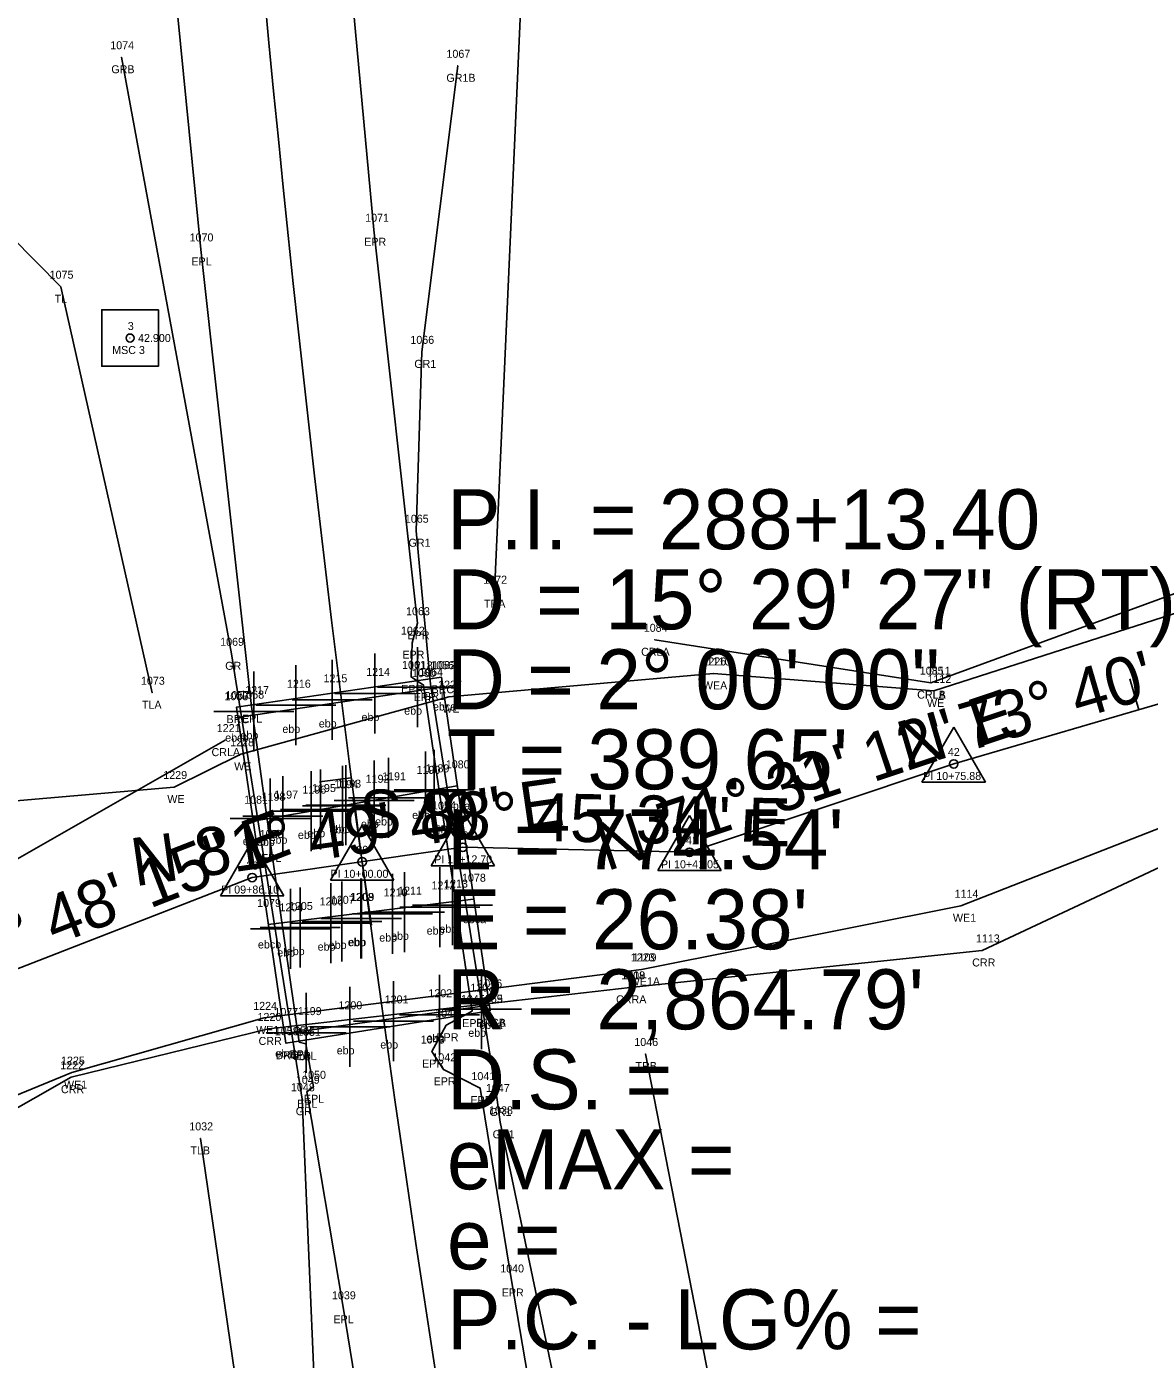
# Model space of a CAD drawing. Extents: x 2445178 to 2446205, y 790762 to 792372.
# Drawn here: x 2445671.4 to 2445811.8, y 791731.8 to 791898.3 of the extents above; entities that cross this region are included whole.
import ezdxf

# ---------------------------------------------------------------- set-up
doc = ezdxf.new("R2010")
doc.units = 0
for name, color, linetype in [('RD_EX_Bridge', 7, 'Continuous'), ('RD_EX_Bridge_txCode', 7, 'Continuous'), ('RD_EX_GuardRail', 7, 'Continuous'), ('RD_EX_GuardRail_txCode', 7, 'Continuous'), ('RD_EX_H2O', 7, 'Continuous'), ('RD_EX_H2O_txCode', 7, 'Continuous'), ('RD_EX_Misc', 7, 'Continuous'), ('RD_EX_Misc_txCode', 7, 'Continuous'), ('RD_EX_Road', 7, 'Continuous'), ('RD_EX_Road_txCode', 7, 'Continuous'), ('RD_EX_VEG', 7, 'Continuous'), ('RD_EX_VEG_txCode', 7, 'Continuous'), ('RD_HC_Cl', 7, 'Continuous'), ('RD_HC_Data', 7, 'Continuous'), ('RD_HC_Data_Tic', 7, 'Continuous'), ('RD_HC_Survey', 7, 'Continuous'), ('RD_HC_txCode', 7, 'Continuous'), ('RD_SMD_Locator', 7, 'Continuous')]:
    doc.layers.add(name, color=color, linetype=linetype)

msp = doc.modelspace()

# ---------------------------------------------------------------- linework, layer by layer
at = {"layer": 'RD_EX_Bridge'}
msp.add_lwpolyline([(2445729.38, 791775.32), (2445723.31, 791817.01), (2445697.69, 791813.27), (2445703.85, 791771.27), (2445729.38, 791775.32)], dxfattribs=at)
at = {"layer": 'RD_EX_GuardRail'}
for points in [[(2445705.68, 791695.08), (2445707.49, 791727.11), (2445705.87, 791764.26), (2445697.05, 791819.94), (2445683.29, 791894.5)], [(2445745.83, 791688.99), (2445730.65, 791761.38), (2445730.26, 791764.17), (2445721.94, 791816.16), (2445720.14, 791835.32), (2445720.85, 791857.68), (2445725.34, 791893.43)]]:
    msp.add_lwpolyline(points, dxfattribs=at)
at = {"layer": 'RD_EX_H2O'}
for points in [[(2445749.98, 791821.69), (2445784.5, 791816.33), (2445784.5, 791816.33), (2445826.97, 791831.85), (2445864.4, 791840.41), (2445865.35, 791848.28), (2445857.59, 791890.6), (2445862.25, 791903.98), (2445902.88, 791935.07), (2445928.13, 791937.54), (2445982.7, 791973.27), (2446006.36, 791974.66), (2446055.29, 791944.59), (2446112.86, 791944.82), (2446116.06, 791949.26), (2446125.53, 791975.87), (2446156.76, 791972.15), (2446187.24, 792018.21)], [(2445757.3, 791817.48), (2445784.85, 791815.29), (2445827.3, 791828.95), (2445865.88, 791838.48), (2445867.77, 791849.3), (2445858.86, 791890.39), (2445863.96, 791902.52), (2445903.58, 791933.29), (2445928.32, 791935.62), (2445983.75, 791971.59), (2446005.28, 791972.74), (2446055.03, 791943.12), (2446113.69, 791943.23), (2446117.06, 791949.31), (2446126.55, 791974.16), (2446158.67, 791970.49), (2446188.67, 792015.57)], [(2445748.32, 791780.49), (2445788.24, 791788.44), (2445846, 791811.01), (2445891.85, 791826.96), (2445872.2, 791885.31), (2445911.58, 791917.24), (2445942.41, 791930.41), (2445989.95, 791963.2), (2446004.43, 791957.67), (2446037.13, 791928.19), (2446062.94, 791924.63), (2446122.42, 791925.89), (2446133.98, 791956.62), (2446163.05, 791958.48), (2446202.11, 792005.16)], [(2445746.88, 791778.25), (2445790.91, 791782.86), (2445846.87, 791809.11), (2445896.01, 791824.25), (2445877, 791883.78), (2445912.26, 791916.16), (2445942.78, 791927.77), (2445991.6, 791962.06), (2446003.69, 791956.06), (2446036.32, 791927.07), (2446060.96, 791923.67), (2446122.97, 791923.97), (2446134.24, 791956.18), (2446163.21, 791958.01), (2446202.51, 792004.24)], [(2445757.3, 791817.48), (2445724.23, 791814.58), (2445698.23, 791807.38), (2445689.87, 791803.29), (2445658, 791800.52), (2445641.81, 791830.07), (2445642.32, 791839.59), (2445634.31, 791862.06), (2445625.81, 791909.02), (2445601.16, 791980.42)], [(2445696.27, 791809.15), (2445652.77, 791784.32), (2445604.79, 791778.94)], [(2445748.32, 791780.49), (2445701.12, 791774.43), (2445677.09, 791767.59), (2445662.39, 791761.56), (2445644.36, 791766.93), (2445623.55, 791762.71), (2445618.49, 791746.46), (2445607.67, 791748.78), (2445606.64, 791748.27), (2445612.18, 791734.98), (2445561.56, 791692.97), (2445554.1, 791670.89), (2445517.8, 791656.91), (2445473.7, 791621.85), (2445363.77, 791592.3), (2445292.26, 791558.82)], [(2445746.88, 791778.25), (2445701.7, 791773.05), (2445676.99, 791767.02), (2445663.02, 791759.06), (2445644.08, 791765.78), (2445608.19, 791764.17)]]:
    msp.add_lwpolyline(points, dxfattribs=at)
at = {"layer": 'RD_EX_Misc'}
for p, q in [((2445714.97, 791809.98), (2445714.97, 791819.98)), ((2445720.31, 791810.78), (2445720.31, 791820.78)), ((2445705.08, 791808.5), (2445705.08, 791818.5)), ((2445709.63, 791809.18), (2445709.63, 791819.18)), ((2445699.83, 791807.71), (2445699.83, 791817.71)), ((2445723.52, 791815.83), (2445697.56, 791811.94)), ((2445709.97, 791814.98), (2445719.97, 791814.98)), ((2445715.31, 791815.78), (2445725.31, 791815.78)), ((2445700.08, 791813.5), (2445710.08, 791813.5)), ((2445704.63, 791814.18), (2445714.63, 791814.18)), ((2445694.83, 791812.71), (2445704.83, 791812.71)), ((2445714.89, 791796.62), (2445714.89, 791806.62)), ((2445716.67, 791796.93), (2445716.67, 791806.93)), ((2445721.3, 791797.73), (2445721.3, 791807.73)), ((2445722.38, 791797.92), (2445722.38, 791807.92)), ((2445707.01, 791795.26), (2445707.01, 791805.26)), ((2445708.19, 791795.46), (2445708.19, 791805.46)), ((2445710.95, 791795.94), (2445710.95, 791805.94)), ((2445711.34, 791796.01), (2445711.34, 791806.01)), ((2445725.27, 791803.42), (2445699.75, 791799)), ((2445701.89, 791794.37), (2445701.89, 791804.37)), ((2445703.46, 791794.64), (2445703.46, 791804.64)), ((2445709.89, 791801.62), (2445719.89, 791801.62)), ((2445711.67, 791801.93), (2445721.67, 791801.93)), ((2445716.3, 791802.73), (2445726.3, 791802.73)), ((2445717.38, 791802.92), (2445727.38, 791802.92)), ((2445702.01, 791800.26), (2445712.01, 791800.26)), ((2445703.19, 791800.46), (2445713.19, 791800.46)), ((2445705.95, 791800.94), (2445715.95, 791800.94)), ((2445706.34, 791801.01), (2445716.34, 791801.01)), ((2445696.89, 791799.37), (2445706.89, 791799.37)), ((2445698.46, 791799.64), (2445708.46, 791799.64)), ((2445723.12, 791783.29), (2445723.12, 791793.29)), ((2445724.7, 791783.52), (2445724.7, 791793.52)), ((2445710.87, 791781.49), (2445710.87, 791791.49)), ((2445713.24, 791781.84), (2445713.24, 791791.84)), ((2445713.32, 791781.85), (2445713.32, 791791.85)), ((2445717.18, 791782.42), (2445717.18, 791792.42)), ((2445718.67, 791782.63), (2445718.67, 791792.63)), ((2445704.44, 791780.55), (2445704.44, 791790.55)), ((2445705.63, 791780.72), (2445705.63, 791790.72)), ((2445709.48, 791781.29), (2445709.48, 791791.29)), ((2445727.27, 791789.25), (2445701.64, 791786.09)), ((2445718.12, 791788.29), (2445728.12, 791788.29)), ((2445719.7, 791788.52), (2445729.7, 791788.52)), ((2445705.87, 791786.49), (2445715.87, 791786.49)), ((2445708.24, 791786.84), (2445718.24, 791786.84)), ((2445708.32, 791786.85), (2445718.32, 791786.85)), ((2445712.18, 791787.42), (2445722.18, 791787.42)), ((2445713.67, 791787.63), (2445723.67, 791787.63)), ((2445699.44, 791785.55), (2445709.44, 791785.55)), ((2445700.63, 791785.72), (2445710.63, 791785.72)), ((2445704.48, 791786.29), (2445714.48, 791786.29)), ((2445723.06, 791769.81), (2445723.06, 791779.81)), ((2445728.31, 791770.52), (2445728.31, 791780.52)), ((2445711.86, 791768.31), (2445711.86, 791778.31)), ((2445717.31, 791769.04), (2445717.31, 791779.04)), ((2445706.41, 791767.58), (2445706.41, 791777.58)), ((2445729.33, 791776.04), (2445703.81, 791772.47)), ((2445718.06, 791774.81), (2445728.06, 791774.81)), ((2445723.31, 791775.52), (2445733.31, 791775.52)), ((2445706.86, 791773.31), (2445716.86, 791773.31)), ((2445712.31, 791774.04), (2445722.31, 791774.04)), ((2445701.41, 791772.58), (2445711.41, 791772.58))]:
    msp.add_line(p, q, dxfattribs=at)
at = {"layer": 'RD_EX_Road'}
for points in [[(2445780.98, 791497.5), (2445766.72, 791558.1), (2445751.9, 791628.3), (2445743.63, 791673.52), (2445732.07, 791741.61), (2445728.16, 791765.65), (2445723.56, 791768), (2445722.11, 791770.23), (2445723.91, 791773.52), (2445727.13, 791775.28), (2445723.51, 791799.48), (2445721.07, 791816.02), (2445719.51, 791817.06), (2445719.65, 791821.33), (2445720.29, 791823.76), (2445714.87, 791872.94), (2445710.18, 791923.37), (2445705.3, 791989.12), (2445702.81, 792033.07), (2445700.66, 792091.77), (2445697.78, 792201.78), (2445695.41, 792302.8)], [(2445850.42, 791174.36), (2445823.13, 791264.7), (2445806.34, 791321.46), (2445789.41, 791379.89), (2445773.46, 791437.57), (2445759.36, 791494.22), (2445744.01, 791559.83), (2445740.09, 791577.64), (2445731.05, 791621.01), (2445722.21, 791669.43), (2445711, 791738.26), (2445706.49, 791765.2), (2445707.32, 791765.82), (2445706.36, 791771.19), (2445705.53, 791771.38), (2445701.96, 791795.92), (2445699.57, 791813.34), (2445693.24, 791870.48), (2445688.14, 791921.92), (2445683.42, 791987.19), (2445680.88, 792033.67), (2445678.74, 792090.55), (2445675.91, 792199.23), (2445673.61, 792301.11)]]:
    msp.add_lwpolyline(points, dxfattribs=at)
at = {"layer": 'RD_EX_VEG'}
for points in [[(2445687.12, 791815.07), (2445675.71, 791865.82), (2445647.64, 791894.24), (2445625.38, 791951.76), (2445599.8, 791999.43), (2445616.22, 792074.95), (2445645.15, 792198.05), (2445661.49, 792301.38)], [(2445729.92, 791827.7), (2445734.27, 791924.48), (2445719.05, 792048.41), (2445719.1, 792091.3), (2445713.04, 792300.82)], [(2445895.98, 791185.85), (2445831.19, 791390.71), (2445805.05, 791501.58), (2445775.97, 791631.01), (2445748.83, 791769.92)], [(2445660.51, 791562.93), (2445719.21, 791580.62), (2445693.16, 791759.37)]]:
    msp.add_lwpolyline(points, dxfattribs=at)
at = {"layer": 'RD_HC_Cl'}
for p, q in [((2445787.35, 791806.17), (2445829.8, 791818.6)), ((2445754.32, 791795.13), (2445787.35, 791806.17)), ((2445699.64, 791791.97), (2445725.97, 791795.75)), ((2445725.97, 791795.75), (2445754.32, 791795.13)), ((2445661.45, 791777.16), (2445699.64, 791791.97))]:
    msp.add_line(p, q, dxfattribs=at)
msp.add_arc((2448553.48, 792169.37), 2864.79, 181.3527, 196.84356, dxfattribs=at)
at = {"layer": 'RD_HC_Data'}
for p, q in [((2445783.38, 791803.88), (2445787.35, 791810.76)), ((2445787.35, 791810.76), (2445791.32, 791803.88)), ((2445783.38, 791803.88), (2445791.32, 791803.88)), ((2445722, 791793.45), (2445725.97, 791800.33)), ((2445725.97, 791800.33), (2445729.94, 791793.45)), ((2445750.35, 791792.84), (2445754.32, 791799.72)), ((2445754.32, 791799.72), (2445758.29, 791792.84)), ((2445709.43, 791791.65), (2445713.4, 791798.53)), ((2445713.4, 791798.53), (2445717.37, 791791.65)), ((2445695.67, 791789.67), (2445699.64, 791796.55)), ((2445699.64, 791796.55), (2445703.61, 791789.67)), ((2445722, 791793.45), (2445729.94, 791793.45)), ((2445709.43, 791791.65), (2445717.37, 791791.65)), ((2445750.35, 791792.84), (2445758.29, 791792.84)), ((2445695.67, 791789.67), (2445703.61, 791789.67))]:
    msp.add_line(p, q, dxfattribs=at)
for centre in [(2445787.35, 791806.17), (2445725.97, 791795.75), (2445754.32, 791795.13), (2445713.4, 791793.94), (2445699.64, 791791.97)]:
    msp.add_circle(centre, 0.529, dxfattribs=at)
at = {"layer": 'RD_HC_Data_Tic'}
for p, q in [((2445810.5, 791812.95), (2445809.38, 791816.79)), ((2445712.03, 791804.43), (2445708.07, 791803.92)), ((2445713.4, 791793.94), (2445712.27, 791801.86)), ((2445713.4, 791793.94), (2445714.54, 791786.02))]:
    msp.add_line(p, q, dxfattribs=at)
at = {"layer": 'RD_HC_Survey'}
msp.add_lwpolyline([(2445687.91, 791862.94), (2445680.84, 791862.94), (2445680.84, 791855.87), (2445687.91, 791855.87)], close=True, dxfattribs=at)
msp.add_circle((2445684.37, 791859.41), 0.5, dxfattribs=at)
at = {"layer": 'RD_SMD_Locator'}
for centre in [(2445683.29, 791894.5), (2445725.34, 791893.43), (2445714.87, 791872.94), (2445693.24, 791870.48), (2445675.71, 791865.82), (2445684.37, 791859.41), (2445720.85, 791857.68), (2445720.14, 791835.32), (2445729.92, 791827.7), (2445720.29, 791823.76), (2445749.98, 791821.69), (2445697.05, 791819.94), (2445719.65, 791821.33), (2445719.51, 791817.06), (2445723.31, 791817.01), (2445757.3, 791817.48), (2445757.3, 791817.48), (2445687.12, 791815.07), (2445721.07, 791816.02), (2445721.94, 791816.16), (2445784.5, 791816.33), (2445784.5, 791816.33), (2445784.85, 791815.29), (2445697.69, 791813.27), (2445699.57, 791813.34), (2445724.23, 791814.58), (2445696.27, 791809.15), (2445698.23, 791807.38), (2445787.35, 791806.17), (2445689.87, 791803.29), (2445723.51, 791799.48), (2445701.96, 791795.92), (2445725.97, 791795.75), (2445754.32, 791795.13), (2445713.4, 791793.94), (2445699.64, 791791.97), (2445788.24, 791788.44), (2445790.91, 791782.86), (2445748.32, 791780.49), (2445748.32, 791780.49), (2445746.88, 791778.25), (2445746.88, 791778.25), (2445727.13, 791775.28), (2445729.38, 791775.32), (2445729.38, 791775.32), (2445701.12, 791774.43), (2445723.91, 791773.52), (2445701.7, 791773.05), (2445703.85, 791771.27), (2445705.53, 791771.38), (2445706.36, 791771.19), (2445722.11, 791770.23), (2445748.83, 791769.92), (2445676.99, 791767.02), (2445677.09, 791767.59), (2445723.56, 791768), (2445706.49, 791765.2), (2445707.32, 791765.82), (2445728.16, 791765.65), (2445705.87, 791764.26), (2445730.26, 791764.17), (2445730.65, 791761.38), (2445693.16, 791759.37), (2445732.07, 791741.61), (2445711, 791738.26)]:
    msp.add_circle(centre, 0.001, dxfattribs=at)

# ---------------------------------------------------------------- texts
at = {"layer": 'RD_EX_Bridge_txCode'}
for s, p in [('1056', (2445721.9, 791818.01)), ('1057', (2445696.3, 791814.27)), ('BRC', (2445722.06, 791815.01)), ('BRC', (2445696.44, 791811.27)), ('1055', (2445727.99, 791776.32)), ('1059', (2445727.99, 791776.32)), ('1058', (2445702.47, 791772.27)), ('BRCA', (2445727.64, 791773.32)), ('BRCB', (2445727.65, 791773.32)), ('BRC', (2445702.6, 791769.27))]:
    msp.add_text(s, height=1, dxfattribs=at).set_placement(p)
at = {"layer": 'RD_EX_GuardRail_txCode'}
for s, p in [('1074', (2445681.9, 791895.5)), ('1067', (2445723.93, 791894.43)), ('GRB', (2445682.03, 791892.5)), ('GR1B', (2445723.92, 791891.43)), ('1066', (2445719.42, 791858.68)), ('GR1', (2445719.91, 791855.68)), ('1065', (2445718.73, 791836.32)), ('GR1', (2445719.19, 791833.32)), ('1069', (2445695.64, 791820.94)), ('GR', (2445696.27, 791817.94)), ('1064', (2445720.53, 791817.16)), ('GR1', (2445721, 791814.16)), ('1048', (2445704.49, 791765.26)), ('1047', (2445728.87, 791765.17)), ('GR', (2445705.09, 791762.26)), ('1038', (2445729.26, 791762.38)), ('GR1', (2445729.31, 791762.17)), ('GR1', (2445729.7, 791759.38))]:
    msp.add_text(s, height=1, dxfattribs=at).set_placement(p)
at = {"layer": 'RD_EX_H2O_txCode'}
for s, p in [('1084', (2445748.6, 791822.69)), ('CRLA', (2445748.27, 791819.69)), ('1226', (2445755.93, 791818.48)), ('1110', (2445756.48, 791818.48)), ('1085', (2445783.11, 791817.33)), ('1111', (2445784, 791817.33)), ('1227', (2445722.89, 791815.58)), ('WEA', (2445755.99, 791815.48)), ('WEA', (2445755.99, 791815.48)), ('1112', (2445784.07, 791816.29)), ('CRLA', (2445782.78, 791814.33)), ('CRLB', (2445782.79, 791814.33)), ('WE', (2445723.4, 791812.58)), ('WE', (2445784.01, 791813.29)), ('1221', (2445695.21, 791810.15)), ('CRLA', (2445694.56, 791807.15)), ('1228', (2445696.89, 791808.38)), ('WE', (2445697.39, 791805.38)), ('1229', (2445688.53, 791804.29)), ('WE', (2445689.03, 791801.29)), ('1114', (2445787.46, 791789.44)), ('WE1', (2445787.25, 791786.44)), ('1113', (2445790.13, 791783.86)), ('1223', (2445746.97, 791781.49)), ('1109', (2445747.21, 791781.49)), ('CRR', (2445789.66, 791780.86)), ('1108', (2445745.78, 791779.25)), ('1219', (2445745.82, 791779.25)), ('WE1A', (2445746.84, 791778.49)), ('WE1A', (2445746.84, 791778.49)), ('1224', (2445699.77, 791775.43)), ('CRRA', (2445745.14, 791776.25)), ('CRRA', (2445745.14, 791776.25)), ('1220', (2445700.31, 791774.05)), ('WE1', (2445700.13, 791772.43)), ('CRR', (2445700.44, 791771.05)), ('1222', (2445675.64, 791768.02)), ('1225', (2445675.74, 791768.59)), ('WE1', (2445676.11, 791765.59)), ('CRR', (2445675.73, 791765.02))]:
    msp.add_text(s, height=1, dxfattribs=at).set_placement(p)
at = {"layer": 'RD_EX_Misc_txCode'}
for s, p in [('1214', (2445713.9, 791817.18)), ('1218', (2445719.24, 791817.98)), ('1082', (2445722.14, 791818.03)), ('1216', (2445703.99, 791815.7)), ('1215', (2445708.56, 791816.38)), ('1083', (2445696.17, 791814.14)), ('1217', (2445698.77, 791814.91)), ('ebo', (2445718.65, 791812.33)), ('ebca', (2445722.24, 791812.85)), ('ebo', (2445707.97, 791810.73)), ('ebo', (2445713.31, 791811.53)), ('ebcb', (2445696.27, 791808.96)), ('ebo', (2445698.18, 791809.27)), ('ebo', (2445703.42, 791810.05)), ('1080', (2445723.85, 791805.62)), ('1192', (2445713.83, 791803.82)), ('1191', (2445715.89, 791804.13)), ('1190', (2445720.19, 791804.93)), ('1189', (2445721.32, 791805.12)), ('1196', (2445705.92, 791802.46)), ('1195', (2445707.13, 791802.66)), ('1194', (2445709.89, 791803.14)), ('1193', (2445710.28, 791803.21)), ('1081', (2445698.64, 791801.2)), ('1198', (2445700.82, 791801.57)), ('1197', (2445702.4, 791801.84)), ('ebca', (2445723.98, 791800.44)), ('ebo', (2445719.64, 791799.29)), ('ebo', (2445706.54, 791797.02)), ('ebo', (2445709.3, 791797.49)), ('ebo', (2445709.69, 791797.56)), ('ebo', (2445713.24, 791798.18)), ('ebo', (2445715.01, 791798.48)), ('ebcb', (2445698.46, 791796.02)), ('ebo', (2445700.23, 791795.92)), ('ebo', (2445701.81, 791796.2)), ('ebo', (2445705.36, 791796.81)), ('1212', (2445722.06, 791790.49)), ('1213', (2445723.64, 791790.72)), ('1078', (2445725.88, 791791.45)), ('1208', (2445711.86, 791789.04)), ('1209', (2445711.94, 791789.05)), ('1210', (2445716.08, 791789.62)), ('1211', (2445717.89, 791789.83)), ('1079', (2445700.26, 791788.29)), ('1204', (2445703.05, 791787.75)), ('1205', (2445704.24, 791787.92)), ('1206', (2445708.07, 791788.49)), ('1207', (2445709.48, 791788.69)), ('ebca', (2445725.98, 791786.27)), ('ebo', (2445715.53, 791783.97)), ('ebo', (2445717.01, 791784.19)), ('ebo', (2445721.46, 791784.84)), ('ebo', (2445723.05, 791785.07)), ('ebcb', (2445700.36, 791783.11)), ('ebo', (2445702.78, 791782.1)), ('ebo', (2445703.97, 791782.28)), ('ebo', (2445707.83, 791782.84)), ('ebo', (2445709.22, 791783.05)), ('ebo', (2445711.59, 791783.39)), ('ebo', (2445711.67, 791783.41)), ('1203', (2445726.93, 791777.72)), ('1076', (2445727.92, 791778.24)), ('1200', (2445710.43, 791775.51)), ('1201', (2445716.21, 791776.24)), ('1202', (2445721.67, 791777.01)), ('1077', (2445702.42, 791774.67)), ('1199', (2445705.35, 791774.78)), ('ebo', (2445726.66, 791772.07)), ('ebca', (2445728.04, 791773.06)), ('ebo', (2445715.66, 791770.6)), ('ebo', (2445721.41, 791771.37)), ('ebcb', (2445702.52, 791769.49)), ('ebo', (2445704.75, 791769.14)), ('ebo', (2445710.21, 791769.87))]:
    msp.add_text(s, height=1, dxfattribs=at).set_placement(p)
at = {"layer": 'RD_EX_Road_txCode'}
for s, p in [('1071', (2445713.77, 791873.94)), ('1070', (2445691.82, 791871.48)), ('EPR', (2445713.65, 791870.94)), ('EPL', (2445692.04, 791868.48)), ('42.900', (2445685.37, 791858.91)), ('1063', (2445718.88, 791824.76)), ('1062', (2445718.24, 791822.33)), ('EPR', (2445719.06, 791821.76)), ('EPR', (2445718.42, 791819.33)), ('1061', (2445718.38, 791818.06)), ('1060', (2445719.62, 791817.02)), ('1068', (2445698.16, 791814.34)), ('EPR', (2445718.28, 791815.06)), ('EPR', (2445719.84, 791814.02)), ('EPL', (2445698.37, 791811.34)), ('1054', (2445722.13, 791800.48)), ('EPR', (2445722.28, 791797.48)), ('1053', (2445700.58, 791796.92)), ('EPL', (2445700.76, 791793.92)), ('1045', (2445725.74, 791776.28)), ('1044', (2445722.52, 791774.52)), ('1052', (2445704.14, 791772.38)), ('1051', (2445705.26, 791772.19)), ('EPR', (2445725.9, 791773.28)), ('1043', (2445720.72, 791771.23)), ('EPR', (2445722.68, 791771.52)), ('EPL', (2445704.32, 791769.38)), ('EPL', (2445705.16, 791769.19)), ('1042', (2445722.17, 791769)), ('EPR', (2445720.88, 791768.23)), ('1049', (2445705.1, 791766.2)), ('1050', (2445705.89, 791766.82)), ('EPR', (2445722.33, 791766)), ('1041', (2445727.05, 791766.65)), ('EPL', (2445706.11, 791763.82)), ('EPL', (2445705.28, 791763.2)), ('EPR', (2445726.93, 791763.65)), ('1040', (2445730.65, 791742.61)), ('1039', (2445709.62, 791739.26)), ('EPR', (2445730.84, 791739.61)), ('EPL', (2445709.8, 791736.26))]:
    msp.add_text(s, height=1, dxfattribs=at).set_placement(p)
at = {"layer": 'RD_EX_VEG_txCode'}
for s, p in [('1075', (2445674.32, 791866.82)), ('TL', (2445674.94, 791863.82)), ('1072', (2445728.53, 791828.7)), ('TRA', (2445728.63, 791825.7)), ('1073', (2445685.74, 791816.07)), ('TLA', (2445685.86, 791813.07)), ('1046', (2445747.42, 791770.92)), ('TRB', (2445747.56, 791767.92)), ('1032', (2445691.78, 791760.37)), ('TLB', (2445691.92, 791757.37))]:
    msp.add_text(s, height=1, dxfattribs=at).set_placement(p)
at = {"layer": 'RD_HC_Data'}
for s, p in [('P.I. = 288+13.40', (2445724, 791833)), ('D', (2445724, 791823)), ('    = 15%%d 29\' 27" (RT)', (2445724, 791823)), ('D = 2%%d 00\' 00"', (2445724, 791813)), ("T = 389.65'", (2445724, 791803)), ("L = 774.54'", (2445724, 791793)), ("E = 26.38'", (2445724, 791783)), ("R = 2,864.79'", (2445724, 791773)), ('D.S. = ', (2445724, 791763)), ('eMAX = ', (2445724, 791753)), ('e = ', (2445724, 791743)), ('P.C. - LG% = ', (2445724, 791733))]:
    msp.add_text(s, height=7.5, dxfattribs=at).set_placement(p)
for s, rotation, p in [('N 73%%d 40\' 41" E', 16.322, (2445781.44, 791805.48)), ('N 71%%d 31\' 12" E', 18.4799, (2445743.98, 791792.73)), ('N 81%%d 49\' 49" E', 8.1698, (2445684.97, 791790.87)), ('S 88%%d 45\' 34" E', 358.7596, (2445712.93, 791797.03)), ('N 68%%d 48\' 15" E', 21.1959, (2445654.1, 791775.38))]:
    msp.add_text(s, height=6, rotation=rotation, dxfattribs=at).set_placement(p)
at = {"layer": 'RD_HC_txCode'}
for s, p in [('3', (2445684.09, 791860.41)), ('MSC 3', (2445682.14, 791857.41)), ('42', (2445786.62, 791807.17)), ('PI 10+75.88', (2445783.53, 791804.17)), ('40', (2445725.2, 791796.75)), ('41', (2445753.87, 791796.13)), ('39', (2445712.67, 791794.94)), ('PI 10+12.70', (2445722.4, 791793.75)), ('38', (2445698.91, 791792.97)), ('PI 10+41.05', (2445750.75, 791793.13)), ('PI 10+00.00', (2445709.42, 791791.94)), ('PI 09+86.10', (2445695.76, 791789.97))]:
    msp.add_text(s, height=1, dxfattribs=at).set_placement(p)

doc.saveas('drawing.dxf')
